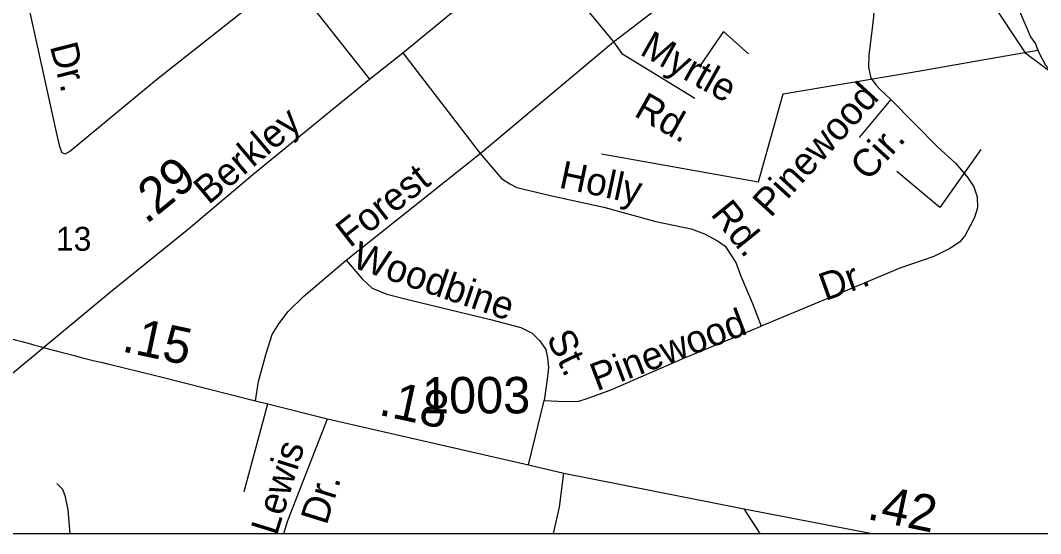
# Model space of a CAD drawing. Extents: x 2315291 to 2336543, y 597177 to 615230.
# Drawn here: x 2321792 to 2325292, y 597529 to 599288 of the extents above; entities that cross this region are included whole.
import ezdxf

# ---------------------------------------------------------------- set-up
doc = ezdxf.new("R2010")
doc.units = 0
for name, color, linetype in [('Exist Boundary Political City Limit New', 7, 'Continuous'), ('Exist Hydrographic Creek Single Shore', 7, 'Continuous'), ('Exist Hydrographic Misc Water Feature', 7, 'Continuous'), ('Exist Road Non-System Type 51', 7, 'Continuous'), ('Exist Road Non-System Type 51 Label', 7, 'Continuous'), ('Exist Road Primary US Attributed', 7, 'Continuous'), ('Exist Road Primary US Label', 7, 'Continuous'), ('Exist Road Primary US Mileage Tenths English Label', 7, 'Continuous'), ('Exist Road Secondary Mileage Hundredths English Label', 7, 'Continuous'), ('Exist Road Secondary Type 51 Attributed', 7, 'Continuous'), ('Exist Road Secondary Type 51 Number Label', 7, 'Continuous'), ('Map Preparation Boundary City Limit Buffer Line', 7, 'Continuous')]:
    doc.layers.add(name, color=color, linetype=linetype)

msp = doc.modelspace()

# ---------------------------------------------------------------- linework, layer by layer
at = {"layer": 'Exist Boundary Political City Limit New'}
msp.add_lwpolyline([(2315744.5, 604723.7), (2315744.5, 597529.5), (2327185.3, 597529.5)], dxfattribs=at)
at = {"layer": 'Exist Hydrographic Creek Single Shore'}
msp.add_lwpolyline([(2325385.4, 599067.9), (2325242.4, 599173.7), (2325115.3, 599365.4), (2325030.4, 599529.4), (2325030.4, 599572), (2325013.4, 599597.6), (2324926.5, 599945.2), (2324925.4, 600053.4), (2324847.3, 600329.2), (2324775.3, 600792.3), (2324741.3, 600886.1), (2324615.4, 601015.5), (2324431.3, 601096.7), (2324329.3, 601187.7), (2324278.3, 601287.4), (2324178.4, 601378.5), (2324052.3, 601419.4), (2323661.3, 601380.6), (2323452.3, 601444.4), (2323301.4, 601520.3), (2323108.3, 601692.9), (2322948.3, 601906.3), (2322863.2, 602047.3), (2322862.4, 602080.1)], dxfattribs=at)
at = {"layer": 'Exist Hydrographic Misc Water Feature'}
for points in [[(2325071.8, 599792.1), (2325076.1, 599766.4), (2325088.4, 599738.1), (2325101.2, 599696.5), (2325125.1, 599634.9), (2325134.2, 599576.8), (2325148.7, 599515), (2325167.4, 599449.3), (2325175.6, 599419.3), (2325198.1, 599373.7), (2325214.6, 599344.1), (2325222.8, 599312), (2325245.1, 599262.4), (2325257.6, 599232.5), (2325274, 599208.6), (2325282.2, 599186.6)], [(2323784.9, 598830.9), (2324323.6, 598734.8), (2324408.3, 599037.2), (2324845, 599110.1), (2325282.2, 599186.6)], [(2325282.2, 599186.6), (2325284.3, 599180.7), (2325308.5, 599134.9), (2325335.1, 599105.3), (2325363.6, 599067.8), (2325395.8, 599036.1), (2325444.4, 599008.6), (2325512.3, 598975.2), (2325558.8, 598955.6), (2325600.9, 598940), (2325649.1, 598920.6), (2325692.7, 598905.5), (2325727.2, 598895.4), (2325755.3, 598881.9), (2325789.1, 598874.3), (2325855.7, 598844.9), (2325910.1, 598821.7), (2325961.8, 598798.1), (2326002.2, 598784.7), (2326029.8, 598780.9), (2326064.1, 598771.4), (2326106.1, 598763.8), (2326148.6, 598750.1), (2326160.7, 598746.3)]]:
    msp.add_lwpolyline(points, dxfattribs=at)
at = {"layer": 'Exist Road Non-System Type 51'}
for p, q in [((2323552, 599546.7), (2323826.4, 599215.3)), ((2322708.5, 599441.8), (2322989.6, 599086.8)), ((2323369.5, 598832.5), (2323826.4, 599215.3)), ((2323103.2, 599177.4), (2323369.5, 598832.5)), ((2324778, 599017.1), (2324669.8, 598887.3)), ((2322909.9, 598465.9), (2323369.5, 598832.5)), ((2322559.2, 597673.8), (2322640.3, 597973.6)), ((2323534.8, 597764.4), (2323588.1, 597984.8)), ((2324330.2, 597529.5), (2324274.6, 597614.2))]:
    msp.add_line(p, q, dxfattribs=at)
for points in [[(2323826.4, 599215.3), (2323995.3, 599344.4), (2324049.4, 599367.4), (2324103.5, 599386.4), (2324215.7, 599424.2), (2324457.6, 599485.1), (2324599.5, 599509.5), (2324633.3, 599505.4), (2324663.1, 599493.2), (2324691.5, 599472.9), (2324713.1, 599448.6), (2324725.3, 599409.4), (2324718.5, 599301.2), (2324713.1, 599251.1), (2324702.7, 599170.3), (2324701, 599128.4), (2324709.5, 599090.5), (2324728, 599066.5), (2324739.4, 599053.4), (2324759, 599035.4), (2324778, 599017.1)], [(2321821.7, 599325.5), (2321916.4, 598895.4), (2321925.8, 598856.2), (2321933.9, 598835.9), (2321944.7, 598830.5), (2321959.6, 598838.6), (2322258.3, 599086.1), (2322708.5, 599441.8)], [(2323826.4, 599215.3), (2323855.1, 599175), (2324105.8, 599022)], [(2324778, 599017.1), (2324938.8, 598854.1), (2324999.7, 598798.7), (2325040.2, 598752.7), (2325063.2, 598717.5), (2325074, 598683.7), (2325075.4, 598645.8), (2325064.5, 598612.6), (2325050.6, 598584), (2325032.1, 598549.8), (2325013.2, 598528.2), (2324980.7, 598506.5), (2324925.3, 598479.5), (2324809.1, 598438.9), (2324559, 598333.4), (2324333.3, 598240.7)], [(2323369.5, 598832.5), (2323442.5, 598746.6), (2323470.8, 598727.7), (2323495.2, 598715.5), (2323615.5, 598687.1), (2323793.9, 598647.9), (2323972.3, 598599.2), (2324092.6, 598573.5), (2324138.6, 598557.2), (2324183.2, 598532.9), (2324210.2, 598514), (2324246.7, 598458.5), (2324263, 598411.2), (2324303.5, 598317.8), (2324333.3, 598240.7)], [(2322598.5, 597983.7), (2322609.1, 598050.5), (2322634.4, 598146), (2322655.5, 598211.1), (2322678.3, 598248.3), (2322710.4, 598290.5), (2322764.5, 598342.9), (2322909.9, 598465.9)], [(2322909.9, 598465.9), (2322964.6, 598402.1), (2322998.4, 598370.8), (2323049.1, 598349.7), (2323130.2, 598329.4), (2323404.7, 598263.5), (2323508.8, 598235.6), (2323547.4, 598216.3), (2323573.1, 598190.6), (2323594.7, 598159.9), (2323600.6, 598131.2), (2323603.1, 598098.4), (2323598.7, 598058.4), (2323594.5, 598025.5), (2323588.1, 597984.8)], [(2323588.1, 597984.8), (2323660.9, 597981.6), (2323707.3, 597983.5), (2323736.6, 597992.5), (2323815.2, 598021.2), (2324068, 598130.6), (2324333.3, 598240.7)], [(2322695.1, 597529.5), (2322708.7, 597574.3), (2322845.6, 597922.3)], [(2323620.7, 597529.5), (2323641.2, 597619.9), (2323656.4, 597736.5)], [(2321962.6, 597529.5), (2321955.3, 597610), (2321946.9, 597655.1), (2321936.9, 597680.2), (2321916.8, 597700.3)]]:
    msp.add_lwpolyline(points, dxfattribs=at)
at = {"layer": 'Exist Road Non-System Type 51 Label'}
for points in [[(2324290, 599174.1), (2324203.5, 599249.9), (2324124.2, 599134.4)], [(2325086.9, 598845.8), (2324946.3, 598647.3), (2324798.4, 598770)]]:
    msp.add_lwpolyline(points, dxfattribs=at)
at = {"layer": 'Exist Road Primary US Attributed'}
msp.add_line((2322091.1, 598110.6), (2322259.2, 598069.4), dxfattribs=at)
for points in [[(2321872.6, 598168.2), (2322100.6, 598357.7), (2322368.8, 598574.3), (2322589.4, 598759.9), (2322822.5, 598950.5), (2322989.6, 599086.8), (2323103.2, 599177.4), (2323552, 599546.7), (2323723.6, 599695.4), (2324757.7, 600529.3), (2324925.6, 600670.6), (2324932.1, 600676), (2324968.9, 600707), (2325301.4, 600984), (2325554.9, 601184.8), (2325709, 601298.4), (2326037.4, 601569.3), (2326353.8, 601821.9), (2326377, 601842), (2326507.1, 601954.4)], [(2321756.1, 598071.9), (2321872.6, 598168.2)]]:
    msp.add_lwpolyline(points, dxfattribs=at)
msp.add_arc((2324469.9, 607823.5), 10000, 254.08936, 256.23807, dxfattribs=at)
at = {"layer": 'Exist Road Secondary Type 51 Attributed'}
msp.add_lwpolyline([(2322259.2, 598069.4), (2322598.5, 597983.7), (2322640.3, 597973.6), (2322845.6, 597922.3), (2323534.8, 597764.4), (2323656.4, 597736.5), (2324274.6, 597614.2), (2324714.3, 597529.5)], dxfattribs=at)
at = {"layer": 'Map Preparation Boundary City Limit Buffer Line'}
msp.add_lwpolyline([(2315744.5, 604723.7), (2315744.5, 597529.5), (2327185.3, 597529.5)], dxfattribs=at)

# ---------------------------------------------------------------- texts
at = {"layer": 'Exist Road Non-System Type 51 Label'}
for s, rotation, p in [('Myrtle', 330.5563, (2323912.9, 599173.7)), ('Dr.', 284.3268, (2321892.2, 599200.1)), ('Pinewood', 47.6164, (2324365.7, 598609.3)), ('Rd.', 330.5563, (2323892.8, 598962.9)), ('Cir.', 47.6164, (2324700.1, 598734)), ('Holly', 347.9697, (2323636.2, 598715.8)), ('Forest', 38.1466, (2322922.1, 598506.5)), ('Rd.', 309.0762, (2324156.7, 598623.4)), ('Woodbine', 341.145, (2322924.5, 598443.4)), ('Dr.', 19.8099, (2324553.1, 598325.9)), ('Pinewood', 20.8257, (2323769.5, 598016.8)), ('St.', 296.079, (2323594.9, 598200.1)), ('Lewis', 72.6954, (2322671.2, 597519.1)), ('Dr.', 72.6954, (2322842, 597555.3))]:
    msp.add_text(s, height=95, rotation=rotation, dxfattribs=at).set_placement(p)
at = {"layer": 'Exist Road Primary US Label'}
msp.add_text('Berkley', height=95, rotation=40.1433, dxfattribs=at).set_placement((2322437.3, 598654.2))
msp.add_text('13', height=82.02, dxfattribs=at).set_placement((2321913.2, 598498.7))
at = {"layer": 'Exist Road Primary US Mileage Tenths English Label'}
msp.add_text('.29', height=125, rotation=39.0884, dxfattribs=at).set_placement((2322223.6, 598587.6))
at = {"layer": 'Exist Road Secondary Mileage Hundredths English Label'}
for s, rotation, p in [('.15', 347.9277, (2322136.3, 598154.4)), ('.18', 347.6104, (2323017.5, 597937)), ('.42', 348.142, (2324692.9, 597579.6))]:
    msp.add_text(s, height=125, rotation=rotation, dxfattribs=at).set_placement(p)
at = {"layer": 'Exist Road Secondary Type 51 Number Label'}
msp.add_text('1003', height=125, dxfattribs=at).set_placement((2323169.2, 597941.1))

doc.saveas('drawing.dxf')
